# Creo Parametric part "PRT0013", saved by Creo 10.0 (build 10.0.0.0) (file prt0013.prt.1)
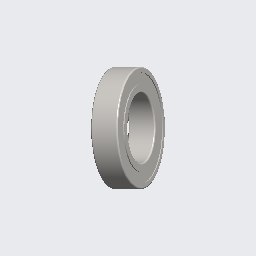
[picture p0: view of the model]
Units: millimeter Newton Second (mmNs); MM, TONNE, SECS

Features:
  1. coordinate system "KUGELLAGER"
  2. imported feature "Import-ke ID 4"

Other named items: NOTE_0

Notes: SS-61801-ZZ-MAE

Surfaces: 16 torus, 12 cylinder, 6 plane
